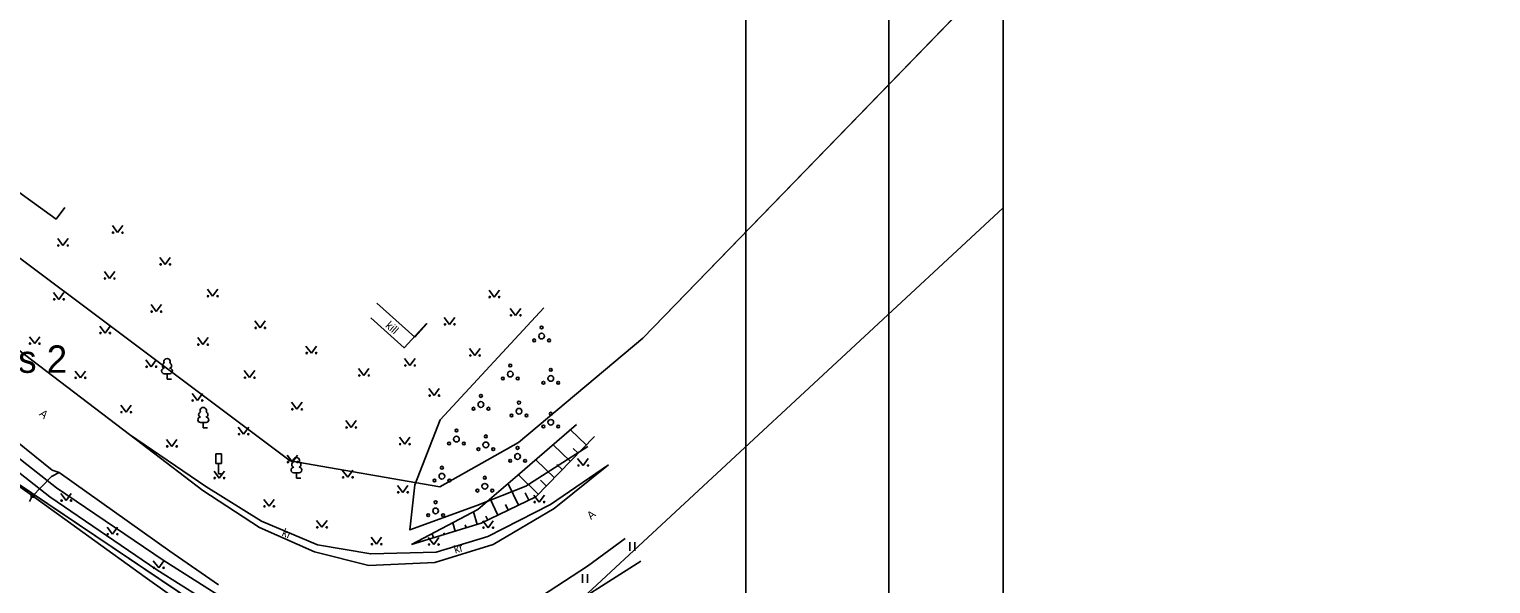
# Model space of a CAD drawing. Extents: x 554947 to 555436, y 6564938 to 6565792.
# Drawn here: x 555307.9 to 555435.7, y 6565528.1 to 6565576.6 of the extents above; entities that cross this region are included whole.
import ezdxf

# ---------------------------------------------------------------- set-up
doc = ezdxf.new("R2010")
doc.units = 0
for name, color, linetype in [('AED', 7, 'Continuous'), ('HALJASTUS', 7, 'Continuous'), ('KASUTUSALA', 7, 'Continuous'), ('LIIKLUS', 7, 'Continuous'), ('PIIR', 7, 'Continuous'), ('PR_SIDE', 7, 'Continuous'), ('PUU', 7, 'Continuous'), ('RELJEEF', 7, 'Continuous'), ('TEE', 7, 'Continuous'), ('VORMISTUS_3', 7, 'Continuous')]:
    doc.layers.add(name, color=color, linetype=linetype)

msp = doc.modelspace()

# ---------------------------------------------------------------- linework, layer by layer
at = {"layer": 'AED'}
for p, q in [((555304.52, 6565538.35), (555308.2, 6565535.79)), ((555308.07, 6565535.91), (555308.07, 6565535.66)), ((555308.07, 6565535.91), (555308.32, 6565535.91)), ((555308.32, 6565535.91), (555308.32, 6565535.66)), ((555308.07, 6565535.66), (555308.32, 6565535.66))]:
    msp.add_line(p, q, dxfattribs=at)
for points in [[(555338.31, 6565552.64), (555341.62, 6565549.67), (555342.69, 6565550.85)], [(555324, 6565524.39), (555318.05, 6565528.67), (555308.2, 6565535.79)]]:
    msp.add_lwpolyline(points, dxfattribs=at)
at = {"layer": 'HALJASTUS'}
for p, q in [((555315.17, 6565559.42), (555315.63, 6565558.81)), ((555315.63, 6565558.81), (555316.08, 6565559.42)), ((555310.39, 6565558.29), (555310.85, 6565557.68)), ((555310.85, 6565557.68), (555311.3, 6565558.29)), ((555319.32, 6565556.64), (555319.79, 6565556.03)), ((555319.79, 6565556.03), (555320.23, 6565556.64)), ((555314.47, 6565555.4), (555314.93, 6565554.79)), ((555314.93, 6565554.79), (555315.38, 6565555.4)), ((555323.48, 6565553.86), (555323.94, 6565553.25)), ((555323.94, 6565553.25), (555324.39, 6565553.86)), ((555310.03, 6565553.58), (555310.49, 6565552.97)), ((555310.49, 6565552.97), (555310.94, 6565553.58)), ((555348.11, 6565553.78), (555348.57, 6565553.17)), ((555348.57, 6565553.17), (555349.02, 6565553.78)), ((555318.55, 6565552.51), (555319.01, 6565551.9)), ((555319.01, 6565551.9), (555319.46, 6565552.51)), ((555344.2, 6565551.39), (555344.66, 6565550.78)), ((555344.66, 6565550.78), (555345.11, 6565551.39)), ((555349.97, 6565552.18), (555350.43, 6565551.57)), ((555350.43, 6565551.57), (555350.88, 6565552.18)), ((555314.07, 6565550.63), (555314.53, 6565550.02)), ((555314.53, 6565550.02), (555314.98, 6565550.63)), ((555327.63, 6565551.08), (555328.1, 6565550.47)), ((555328.1, 6565550.47), (555328.54, 6565551.08)), ((555307.91, 6565549.7), (555308.38, 6565549.1)), ((555308.38, 6565549.1), (555308.82, 6565549.7)), ((555322.63, 6565549.62), (555323.09, 6565549.01)), ((555323.09, 6565549.01), (555323.54, 6565549.62)), ((555332.1, 6565548.88), (555332.57, 6565548.27)), ((555332.57, 6565548.27), (555333.01, 6565548.88)), ((555318.11, 6565547.68), (555318.57, 6565547.07)), ((555318.57, 6565547.07), (555319.01, 6565547.68)), ((555340.73, 6565547.79), (555341.19, 6565547.18)), ((555341.19, 6565547.18), (555341.64, 6565547.79)), ((555346.41, 6565548.67), (555346.88, 6565548.06)), ((555346.88, 6565548.06), (555347.32, 6565548.67)), ((555311.91, 6565546.7), (555312.38, 6565546.1)), ((555312.38, 6565546.1), (555312.82, 6565546.7)), ((555326.71, 6565546.73), (555327.17, 6565546.12)), ((555327.17, 6565546.12), (555327.62, 6565546.73)), ((555336.7, 6565546.92), (555337.17, 6565546.31)), ((555337.17, 6565546.31), (555337.61, 6565546.92)), ((555342.85, 6565545.16), (555343.32, 6565544.55)), ((555343.32, 6565544.55), (555343.76, 6565545.16)), ((555315.91, 6565543.7), (555316.37, 6565543.1)), ((555316.37, 6565543.1), (555316.82, 6565543.7)), ((555322.14, 6565544.73), (555322.61, 6565544.12)), ((555322.61, 6565544.12), (555323.05, 6565544.73)), ((555330.85, 6565543.96), (555331.31, 6565543.35)), ((555331.31, 6565543.35), (555331.76, 6565543.96)), ((555335.59, 6565542.37), (555336.05, 6565541.76)), ((555336.05, 6565541.76), (555336.5, 6565542.37)), ((555326.18, 6565541.78), (555326.64, 6565541.17)), ((555326.64, 6565541.17), (555327.09, 6565541.78)), ((555319.91, 6565540.7), (555320.37, 6565540.1)), ((555320.37, 6565540.1), (555320.82, 6565540.7)), ((555340.28, 6565540.91), (555340.74, 6565540.3)), ((555340.74, 6565540.3), (555341.19, 6565540.91)), ((555330.46, 6565539.34), (555330.93, 6565538.73)), ((555330.93, 6565538.73), (555331.37, 6565539.34)), ((555355.86, 6565539.03), (555356.33, 6565538.43)), ((555356.33, 6565538.43), (555356.77, 6565539.03)), ((555324.06, 6565537.93), (555324.52, 6565537.33)), ((555324.52, 6565537.33), (555324.97, 6565537.93)), ((555335.28, 6565538.01), (555335.75, 6565537.4)), ((555335.75, 6565537.4), (555336.19, 6565538.01)), ((555310.67, 6565535.97), (555311.13, 6565535.36)), ((555311.13, 6565535.36), (555311.58, 6565535.97)), ((555340.1, 6565536.68), (555340.57, 6565536.08)), ((555340.57, 6565536.08), (555341.01, 6565536.68)), ((555328.41, 6565535.46), (555328.87, 6565534.86)), ((555328.87, 6565534.86), (555329.32, 6565535.46)), ((555352.04, 6565535.83), (555352.5, 6565535.23)), ((555352.5, 6565535.23), (555352.95, 6565535.83)), ((555333.03, 6565533.63), (555333.49, 6565533.02)), ((555333.49, 6565533.02), (555333.94, 6565533.63)), ((555347.57, 6565533.59), (555348.03, 6565532.99)), ((555348.03, 6565532.99), (555348.48, 6565533.59)), ((555314.71, 6565533.03), (555315.17, 6565532.42)), ((555315.17, 6565532.42), (555315.62, 6565533.03)), ((555337.81, 6565532.15), (555338.27, 6565531.55)), ((555338.27, 6565531.55), (555338.72, 6565532.15)), ((555342.8, 6565532.13), (555343.27, 6565531.52)), ((555343.27, 6565531.52), (555343.71, 6565532.13)), ((555360.41, 6565531.73), (555360.41, 6565530.97)), ((555360.86, 6565531.73), (555360.86, 6565530.97)), ((555318.75, 6565530.09), (555319.22, 6565529.48)), ((555319.22, 6565529.48), (555319.66, 6565530.09)), ((555356.27, 6565528.92), (555356.27, 6565528.16)), ((555356.72, 6565528.92), (555356.72, 6565528.16))]:
    msp.add_line(p, q, dxfattribs=at)
for points in [[(555352.89, 6565552.22), (555343.84, 6565542.42), (555341.63, 6565536.75), (555341.19, 6565532.8), (555347.05, 6565534.92), (555351.32, 6565536.63), (555356.76, 6565540.09)], [(555361.38, 6565530.07), (555353.3, 6565524.93), (555351.72, 6565521.85), (555350.97, 6565518.73), (555353.48, 6565515.91)]]:
    msp.add_lwpolyline(points, dxfattribs=at)
for centre in [(555310.45, 6565557.68), (555311.28, 6565557.68), (555315.23, 6565558.81), (555316.06, 6565558.81), (555319.39, 6565556.03), (555320.21, 6565556.03), (555314.53, 6565554.79), (555315.36, 6565554.79), (555310.09, 6565552.97), (555310.92, 6565552.97), (555323.54, 6565553.25), (555324.37, 6565553.25), (555348.17, 6565553.17), (555349, 6565553.17), (555318.61, 6565551.9), (555319.44, 6565551.9), (555350.03, 6565551.57), (555350.86, 6565551.57), (555314.13, 6565550.02), (555314.96, 6565550.02), (555327.7, 6565550.47), (555328.52, 6565550.47), (555344.26, 6565550.78), (555345.09, 6565550.78), (555307.97, 6565549.1), (555308.8, 6565549.1), (555322.69, 6565549.01), (555323.52, 6565549.01), (555332.17, 6565548.27), (555332.99, 6565548.27), (555346.47, 6565548.06), (555347.3, 6565548.06), (555311.97, 6565546.1), (555312.8, 6565546.1), (555318.17, 6565547.07), (555319, 6565547.07), (555326.77, 6565546.12), (555327.6, 6565546.12), (555336.77, 6565546.31), (555337.6, 6565546.31), (555340.79, 6565547.18), (555341.62, 6565547.18), (555322.2, 6565544.12), (555323.03, 6565544.12), (555342.92, 6565544.55), (555343.74, 6565544.55), (555315.97, 6565543.1), (555316.8, 6565543.1), (555330.91, 6565543.35), (555331.74, 6565543.35), (555326.24, 6565541.17), (555327.07, 6565541.17), (555335.65, 6565541.76), (555336.48, 6565541.76), (555319.97, 6565540.1), (555320.8, 6565540.1), (555340.34, 6565540.3), (555341.17, 6565540.3), (555330.53, 6565538.73), (555331.36, 6565538.73), (555355.93, 6565538.43), (555356.76, 6565538.43), (555324.12, 6565537.33), (555324.95, 6565537.33), (555335.35, 6565537.4), (555336.18, 6565537.4), (555340.17, 6565536.08), (555341, 6565536.08), (555310.73, 6565535.36), (555311.56, 6565535.36), (555328.47, 6565534.86), (555329.3, 6565534.86), (555352.1, 6565535.23), (555352.93, 6565535.23), (555314.77, 6565532.42), (555315.6, 6565532.42), (555333.09, 6565533.02), (555333.92, 6565533.02), (555347.63, 6565532.99), (555348.46, 6565532.99), (555337.87, 6565531.55), (555338.7, 6565531.55), (555342.87, 6565531.52), (555343.7, 6565531.52), (555318.82, 6565529.48), (555319.65, 6565529.48)]:
    msp.add_circle(centre, 0.055, dxfattribs=at)
at = {"layer": 'KASUTUSALA'}
msp.add_lwpolyline([(555304.52, 6565541), (555310.28, 6565536.49), (555319.6, 6565530.14), (555323.85, 6565527.46), (555330.76, 6565523.11), (555337.95, 6565518.8), (555340.91, 6565516.06), (555343.38, 6565512.73), (555343.14, 6565512.46), (555338.79, 6565515.38), (555330.79, 6565520.76), (555305.2, 6565537.96)], dxfattribs=at)
at = {"layer": 'LIIKLUS'}
for p, q in [((555324.21, 6565539.45), (555324.21, 6565538.6)), ((555324.71, 6565539.45), (555324.21, 6565539.45)), ((555324.71, 6565538.6), (555324.21, 6565538.6)), ((555324.46, 6565538.6), (555324.46, 6565537.7)), ((555324.71, 6565539.45), (555324.71, 6565538.6)), ((555324.71, 6565537.7), (555324.46, 6565537.7))]:
    msp.add_line(p, q, dxfattribs=at)
at = {"layer": 'PIIR'}
for points in [[(555374.15, 6565660.24), (555410.9, 6565638.65), (555418.94, 6565635.85), (555435.71, 6565632.72), (555428.83, 6565620.98), (555419.65, 6565609.54), (555361.56, 6565549.57), (555350.68, 6565540.44), (555343.81, 6565536.56), (555330.71, 6565538.85), (555251.24, 6565598.48), (555234.35, 6565605.6), (555223.17, 6565668.21)], [(555144.16, 6565410.6), (555124.27, 6565454.45), (555113.82, 6565475.68), (555076.76, 6565542.38), (555065.78, 6565566.7), (555060.42, 6565583.26), (555057.22, 6565600.73), (555056.61, 6565622.91), (555063.43, 6565647.29), (555114.24, 6565634), (555129.77, 6565611.2), (555130.73, 6565621.32), (555138.66, 6565615.26), (555160.12, 6565598.86), (555193.24, 6565604.68), (555193.7, 6565602.7), (555225.47, 6565605.89), (555234.35, 6565605.6), (555251.24, 6565598.48), (555330.71, 6565538.85), (555343.81, 6565536.56), (555350.68, 6565540.44), (555361.56, 6565549.57), (555393.07, 6565582.1)], [(555393.07, 6565560.97), (555353.12, 6565523.87), (555343.14, 6565512.46), (555302.6, 6565539.71), (555242.37, 6565583.94), (555179.42, 6565586.32), (555138.98, 6565580.6), (555121.18, 6565602.26), (555116.17, 6565610.5), (555109.96, 6565624.83), (555093.56, 6565628.47), (555079.04, 6565618.4), (555074.13, 6565607.82), (555075.34, 6565593.24), (555091.74, 6565551.94), (555171.91, 6565394.64), (555191.35, 6565341.19), (555195.08, 6565294.61), (555195.28, 6565271.63), (555191.64, 6565237.48)], [(555393.07, 6565456.05), (555368.05, 6565461.11), (555358.8, 6565482.45), (555353.12, 6565523.87), (555393.07, 6565560.97)]]:
    msp.add_lwpolyline(points, dxfattribs=at)
msp.add_lwpolyline([(555153.01, 6565448.47), (555161.15, 6565451.45), (555173.66, 6565456.03), (555207.29, 6565506.14), (555287.77, 6565518.56), (555302.6, 6565539.71), (555343.14, 6565512.46), (555319.44, 6565481.04), (555323.07, 6565461.26), (555312.9, 6565433.84), (555316.84, 6565372.52), (555318.72, 6565342.57), (555320.51, 6565314.61), (555303.13, 6565302.54), (555208.78, 6565303.3), (555205.15, 6565297.11), (555200.72, 6565310.3), (555206.9, 6565339.44), (555221.23, 6565376.06), (555216.83, 6565392.35), (555207.22, 6565406.57)], close=True, dxfattribs=at)
at = {"layer": 'PR_SIDE'}
msp.add_lwpolyline([(555393.07, 6565447.47), (555392.75, 6565447.53), (555372.33, 6565450.45), (555366.01, 6565452.34), (555363.26, 6565453.63), (555360.29, 6565456.79), (555356.82, 6565461.86), (555353.75, 6565469.93), (555350.28, 6565487.81), (555348.6, 6565498.75), (555346.2, 6565508), (555346.03, 6565508.33), (555343.44, 6565510.97), (555340.16, 6565515.39), (555337.34, 6565518), (555330.24, 6565522.26), (555323.32, 6565526.61), (555319.05, 6565529.3), (555309.69, 6565535.68), (555303.92, 6565540.2)], dxfattribs=at)
at = {"layer": 'PUU'}
for p, q in [((555320.19, 6565546.46), (555319.71, 6565546.46)), ((555319.95, 6565545.99), (555319.95, 6565546.46)), ((555320.33, 6565545.99), (555319.95, 6565545.99)), ((555323.36, 6565542.2), (555322.88, 6565542.2)), ((555323.12, 6565541.72), (555323.12, 6565542.2)), ((555323.5, 6565541.72), (555323.12, 6565541.72)), ((555331.5, 6565537.8), (555331.02, 6565537.8)), ((555331.26, 6565537.33), (555331.26, 6565537.8)), ((555331.64, 6565537.33), (555331.26, 6565537.33))]:
    msp.add_line(p, q, dxfattribs=at)
for centre, radius in [((555352.71, 6565549.76), 0.25), ((555352.71, 6565550.51), 0.125), ((555352.06, 6565549.38), 0.125), ((555353.36, 6565549.38), 0.125), ((555349.32, 6565546.05), 0.125), ((555349.97, 6565546.43), 0.25), ((555349.97, 6565547.18), 0.125), ((555350.62, 6565546.05), 0.125), ((555353.51, 6565546.05), 0.25), ((555353.51, 6565546.8), 0.125), ((555352.86, 6565545.67), 0.125), ((555354.16, 6565545.67), 0.125), ((555347.4, 6565543.77), 0.25), ((555347.4, 6565544.52), 0.125), ((555350.73, 6565543.93), 0.125), ((555346.75, 6565543.4), 0.125), ((555348.05, 6565543.4), 0.125), ((555350.08, 6565542.81), 0.125), ((555350.73, 6565543.18), 0.25), ((555351.38, 6565542.81), 0.125), ((555353.51, 6565542.21), 0.25), ((555353.51, 6565542.96), 0.125), ((555345.26, 6565541.49), 0.125), ((555347.83, 6565540.98), 0.125), ((555352.86, 6565541.84), 0.125), ((555354.16, 6565541.84), 0.125), ((555344.61, 6565540.36), 0.125), ((555345.26, 6565540.74), 0.25), ((555345.91, 6565540.36), 0.125), ((555347.18, 6565539.86), 0.125), ((555347.83, 6565540.23), 0.25), ((555348.48, 6565539.86), 0.125), ((555350.61, 6565539.97), 0.125), ((555349.96, 6565538.84), 0.125), ((555350.61, 6565539.22), 0.25), ((555351.26, 6565538.84), 0.125), ((555343.34, 6565537.12), 0.125), ((555343.99, 6565537.49), 0.25), ((555343.99, 6565538.24), 0.125), ((555344.64, 6565537.12), 0.125), ((555347.74, 6565537.36), 0.125), ((555347.09, 6565536.23), 0.125), ((555347.74, 6565536.61), 0.25), ((555348.39, 6565536.23), 0.125), ((555343.44, 6565534.46), 0.25), ((555343.44, 6565535.21), 0.125), ((555342.79, 6565534.08), 0.125), ((555344.09, 6565534.08), 0.125)]:
    msp.add_circle(centre, radius, dxfattribs=at)
for centre, radius, start, end in [((555319.95, 6565547.51), 0.277, 332.5799, 207.4201), ((555319.71, 6565546.7), 0.238, 90.0016, 269.3953), ((555319.78, 6565547.16), 0.233, 109.0217, 253.1415), ((555320.12, 6565547.16), 0.233, 286.8508, 70.9859), ((555320.18, 6565546.7), 0.238, 270.6047, 89.9984), ((555322.88, 6565542.43), 0.238, 90.0016, 269.3953), ((555322.95, 6565542.89), 0.233, 109.0217, 253.1415), ((555323.12, 6565543.24), 0.277, 332.5799, 207.4201), ((555323.29, 6565542.89), 0.233, 286.8508, 70.9859), ((555323.36, 6565542.43), 0.238, 270.6047, 89.9984), ((555331.09, 6565538.5), 0.233, 109.0217, 253.1415), ((555331.26, 6565538.85), 0.277, 332.5799, 207.4201), ((555331.43, 6565538.5), 0.233, 286.8508, 70.9859), ((555331.03, 6565538.04), 0.238, 90.0016, 269.3953), ((555331.5, 6565538.04), 0.238, 270.6047, 89.9984)]:
    msp.add_arc(centre, radius, start, end, dxfattribs=at)
at = {"layer": 'RELJEEF'}
for p, q in [((555356.6, 6565540.23), (555355.24, 6565541.56)), ((555355.21, 6565538.8), (555353.72, 6565540.25)), ((555355.91, 6565539.52), (555355.48, 6565539.93)), ((555353.82, 6565537.36), (555352.2, 6565538.93)), ((555354.51, 6565538.08), (555354.05, 6565538.53)), ((555352.42, 6565535.93), (555350.68, 6565537.62)), ((555350.69, 6565534.96), (555349.78, 6565536.84)), ((555351.59, 6565535.4), (555351.28, 6565536.03)), ((555353.12, 6565536.65), (555352.62, 6565537.14)), ((555348.89, 6565534.09), (555348.21, 6565535.5)), ((555349.79, 6565534.52), (555349.55, 6565535.02)), ((555345.16, 6565532.68), (555344.94, 6565533.42)), ((555347.07, 6565533.26), (555346.74, 6565534.37)), ((555347.99, 6565533.65), (555347.82, 6565534)), ((555343.25, 6565532.1), (555343.14, 6565532.46)), ((555344.21, 6565532.39), (555344.16, 6565532.55)), ((555346.12, 6565532.97), (555346.03, 6565533.25)), ((555342.29, 6565531.8), (555342.28, 6565531.86))]:
    msp.add_line(p, q, dxfattribs=at)
for points in [[(555341.34, 6565531.51), (555347.14, 6565534.58), (555350.61, 6565537.56), (555355.77, 6565542.02)], [(555341.34, 6565531.51), (555347.42, 6565533.37), (555352.19, 6565535.69), (555357.33, 6565540.98)]]:
    msp.add_lwpolyline(points, dxfattribs=at)
at = {"layer": 'TEE'}
for points in [[(555272.68, 6565590.13), (555271.48, 6565588.08), (555270.52, 6565586.42), (555269.72, 6565584.61), (555268.98, 6565582.24), (555268.55, 6565578.95), (555269.5, 6565576.95), (555281.04, 6565568.1), (555297.77, 6565555.51), (555316.66, 6565541.13), (555323.07, 6565536.25), (555328.04, 6565533.01), (555332.84, 6565530.88), (555337.61, 6565529.69), (555343.36, 6565529.95), (555348.46, 6565531.53), (555353.8, 6565534.68), (555358.56, 6565538.5)], [(555293.36, 6565574.44), (555292.54, 6565573.05), (555305.07, 6565563.71), (555310.25, 6565559.99), (555311.01, 6565561)], [(555337.76, 6565551.34), (555340.69, 6565548.73), (555342.63, 6565550.87)], [(555324.45, 6565528), (555320.2, 6565530.94), (555310.53, 6565537.81), (555309.91, 6565538.03), (555305.17, 6565541.81)], [(555316.66, 6565541.13), (555323.34, 6565536.58), (555328.21, 6565533.55), (555333.12, 6565531.48), (555337.76, 6565530.7), (555343.48, 6565530.86), (555348.01, 6565532.22), (555353.48, 6565535.01), (555358.56, 6565538.5)], [(555310.53, 6565537.81), (555309.86, 6565537.47), (555308.14, 6565535.69), (555307.92, 6565535.29)], [(555360.02, 6565532.03), (555356.72, 6565529.61), (555352.04, 6565526.57), (555350.84, 6565524.29), (555349.9, 6565522.25), (555349.37, 6565518.74), (555349.97, 6565514.97), (555351.5, 6565509.51), (555352.4, 6565505.44), (555355.18, 6565489.69), (555356.36, 6565481.87), (555358.54, 6565472.03), (555360.2, 6565467.29), (555362.13, 6565463.39), (555365, 6565459.53), (555367.92, 6565457.75), (555371.76, 6565456.51), (555378.11, 6565454.85), (555393.07, 6565452.68)]]:
    msp.add_lwpolyline(points, dxfattribs=at)
at = {"layer": 'VORMISTUS_3'}
for points in [[(555183.07, 6565701.75), (555393.07, 6565701.75), (555393.07, 6565404.75), (555183.07, 6565404.75)], [(555193.07, 6565415.75), (555383.07, 6565415.75), (555383.07, 6565690.75), (555193.07, 6565690.75)], [(555193.07, 6565690.75), (555383.07, 6565690.75), (555383.07, 6565415.75), (555193.07, 6565415.75)], [(555370.57, 6565441.75), (555205.57, 6565441.75), (555205.57, 6565651.75), (555370.57, 6565651.75)]]:
    msp.add_lwpolyline(points, close=True, dxfattribs=at)

# ---------------------------------------------------------------- texts
at = {"layer": 'TEE'}
for s, rotation, p in [('kill', 318.3864, (555339, 6565550.6)), ('A', 320.7112, (555308.71, 6565542.86)), ('A', 40.0399, (555357.03, 6565533.65)), ('kr', 336.0366, (555329.94, 6565532.31)), ('kr', 17.2462, (555345.16, 6565530.72))]:
    msp.add_text(s, height=0.7, rotation=rotation, dxfattribs=at).set_placement(p)
at = {"layer": 'VORMISTUS_3'}
msp.add_text('Pos 2', height=2.4, dxfattribs=at).set_placement((555303.01, 6565546.54))

doc.saveas('drawing.dxf')
